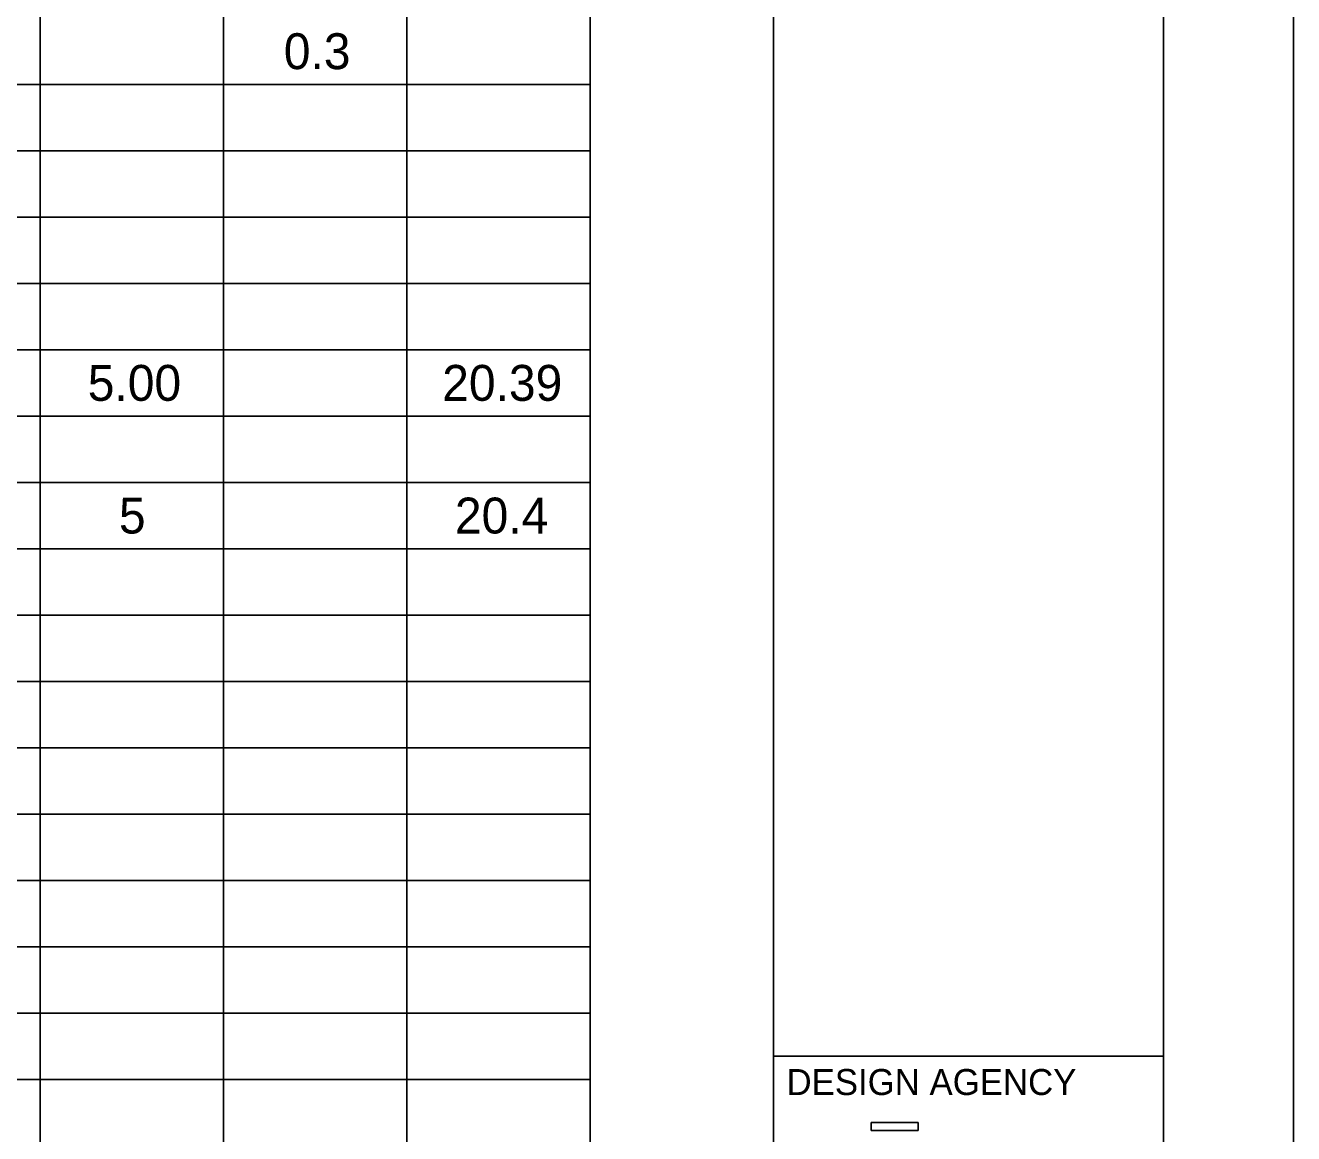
# Model space of a CAD drawing. Extents: x 0 to 34, y 0 to 22.
# Drawn here: x 29.123 to 34, y 4.202 to 8.462 of the extents above; entities that cross this region are included whole.
import ezdxf

# ---------------------------------------------------------------- set-up
doc = ezdxf.new("R2010")
doc.units = 0
for name, color, linetype in [('SH_Border', 7, 'Continuous'), ('SH_Cut_Line', 7, 'Continuous'), ('SH_Data', 7, 'Continuous'), ('SH_Text', 7, 'Continuous')]:
    doc.layers.add(name, color=color, linetype=linetype)

msp = doc.modelspace()

# ---------------------------------------------------------------- linework, layer by layer
at = {"layer": 'SH_Border'}
for p, q in [((32, 0.5), (32, 21.5)), ((32, 4.5), (33.5, 4.5))]:
    msp.add_line(p, q, dxfattribs=at)
msp.add_lwpolyline([(1.5, 21.5), (33.5, 21.5), (33.5, 0.5), (1.5, 0.5)], close=True, dxfattribs=at)
at = {"layer": 'SH_Cut_Line'}
msp.add_lwpolyline([(0, 0), (34, 0), (34, 22), (0, 22)], close=True, dxfattribs=at)
at = {"layer": 'SH_Data'}
for p, q in [((32.3756, 4.2141), (32.3756, 4.244)), ((32.3756, 4.244), (32.5557, 4.244)), ((32.5557, 4.244), (32.5557, 4.2141)), ((32.5557, 4.2141), (32.3756, 4.2141))]:
    msp.add_line(p, q, dxfattribs=at)
msp.add_lwpolyline([(32.3756, 4.2141), (32.3756, 4.244), (32.5557, 4.244), (32.5557, 4.2141)], close=True, dxfattribs=at)
at = {"layer": 'SH_Text'}
for p, q in [((29.885, 21), (29.885, 2.625)), ((31.295, 21), (31.295, 2.625)), ((29.18, 20.745), (29.18, 2.625)), ((30.59, 20.745), (30.59, 2.625)), ((14.42, 8.235), (31.295, 8.235)), ((14.42, 7.98), (31.295, 7.98)), ((14.42, 7.725), (31.295, 7.725)), ((14.42, 7.47), (31.295, 7.47)), ((14.42, 7.215), (31.295, 7.215)), ((14.42, 6.96), (31.295, 6.96)), ((14.42, 6.705), (31.295, 6.705)), ((14.42, 6.45), (31.295, 6.45)), ((14.42, 6.195), (31.295, 6.195)), ((14.42, 5.94), (31.295, 5.94)), ((14.42, 5.685), (31.295, 5.685)), ((14.42, 5.43), (31.295, 5.43)), ((14.42, 5.175), (31.295, 5.175)), ((14.42, 4.92), (31.295, 4.92)), ((14.42, 4.665), (31.295, 4.665)), ((14.42, 4.41), (31.295, 4.41))]:
    msp.add_line(p, q, dxfattribs=at)

# ---------------------------------------------------------------- texts
at = {"layer": 'SH_Data'}
msp.add_text('DESIGN AGENCY', height=0.1, dxfattribs=at).set_placement((32.05, 4.35))
at = {"layer": 'SH_Text'}
for s, p in [('0.3', (30.1168, 8.2935)), ('5.00', (29.3629, 7.0185)), ('20.39', (30.7259, 7.0185)), ('5', (29.4828, 6.5085)), ('20.4', (30.7748, 6.5085))]:
    msp.add_text(s, height=0.138, dxfattribs=at).set_placement(p)

doc.saveas('drawing.dxf')
